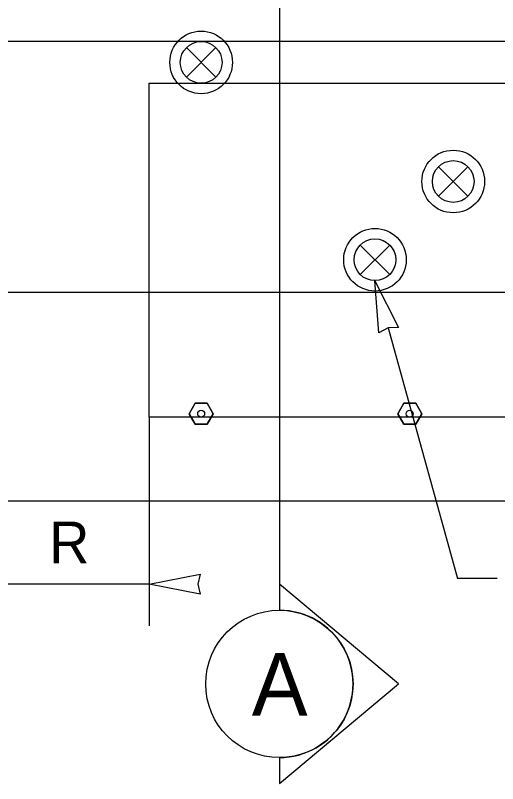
# Model space of a CAD drawing. Extents: x 99958 to 100176, y 99935 to 100011.
# Drawn here: x 100010.207 to 100011.132, y 99974.193 to 99975.666 of the extents above; entities that cross this region are included whole.
import ezdxf

# ---------------------------------------------------------------- set-up
doc = ezdxf.new("R2010")
doc.units = 0
for name, color, linetype in [('RD_ED_ShoulderPavedEdge', 7, 'Continuous'), ('RD_MK_LineEdgeWhite', 7, 'Continuous'), ('RD_MK_LineLane', 7, 'Continuous'), ('SH_TI_WZSectionCut', 7, 'Continuous'), ('TR_WZ_TrafficSafetyDrum', 7, 'Continuous'), ('TR_WZ_TubularMarker', 7, 'Continuous'), ('TR_WZ_WorkZoneDetails', 7, 'Continuous'), ('TR_WZ_WorkZoneTextCurrent', 7, 'Continuous')]:
    doc.layers.add(name, color=color, linetype=linetype)

msp = doc.modelspace()

# ---------------------------------------------------------------- linework, layer by layer
at = {"layer": 'RD_ED_ShoulderPavedEdge'}
msp.add_line((100000.8283, 99974.7357), (100014.8933, 99974.7357), dxfattribs=at)
at = {"layer": 'RD_MK_LineEdgeWhite'}
msp.add_line((100000.8283, 99975.1357), (100014.8933, 99975.1357), dxfattribs=at)
at = {"layer": 'RD_MK_LineLane'}
msp.add_lwpolyline([(100014.8933, 99975.6157), (100000.8283, 99975.6157)], dxfattribs=at)
at = {"layer": 'SH_TI_WZSectionCut'}
for p, q in [((100010.7136, 99976.1157), (100010.7136, 99974.5757)), ((100010.7136, 99974.5757), (100010.7136, 99974.5258)), ((100010.9417, 99974.3846), (100010.7136, 99974.5757)), ((100010.7136, 99974.1935), (100010.9417, 99974.3846)), ((100010.7136, 99974.2434), (100010.7136, 99974.1935))]:
    msp.add_line(p, q, dxfattribs=at)
msp.add_circle((100010.7136, 99974.3846), 0.1412, dxfattribs=at)
msp.add_arc((100010.7136, 99974.3846), 0.1412, 269.9978, 90.0022, dxfattribs=at)
at = {"layer": 'TR_WZ_TrafficSafetyDrum'}
for p, q in [((100010.5353, 99975.604), (100010.5919, 99975.5474)), ((100010.5919, 99975.604), (100010.5353, 99975.5474)), ((100011.0752, 99975.3192), (100011.0186, 99975.3757)), ((100011.0186, 99975.3192), (100011.0752, 99975.3757)), ((100010.9252, 99975.1692), (100010.8686, 99975.2257)), ((100010.8686, 99975.1692), (100010.9252, 99975.2257))]:
    msp.add_line(p, q, dxfattribs=at)
for centre, radius in [((100010.5636, 99975.5757), 0.06), ((100010.5636, 99975.5757), 0.06), ((100010.5636, 99975.5757), 0.04), ((100011.0469, 99975.3475), 0.06), ((100011.0469, 99975.3475), 0.06), ((100011.0469, 99975.3475), 0.04), ((100010.8969, 99975.1975), 0.06), ((100010.8969, 99975.1975), 0.06), ((100010.8969, 99975.1975), 0.04)]:
    msp.add_circle(centre, radius, dxfattribs=at)
at = {"layer": 'TR_WZ_TubularMarker'}
for points in [[(100010.5405, 99974.9024), (100010.5521, 99974.9224), (100010.5752, 99974.9224), (100010.5867, 99974.9024), (100010.5752, 99974.8824), (100010.5521, 99974.8824)], [(100010.9405, 99974.9024), (100010.9521, 99974.9224), (100010.9752, 99974.9224), (100010.9867, 99974.9024), (100010.9752, 99974.8824), (100010.9521, 99974.8824)]]:
    msp.add_lwpolyline(points, close=True, dxfattribs=at)
for points in [[(100010.5521, 99974.8824), (100010.5752, 99974.8824), (100010.5867, 99974.9024), (100010.5752, 99974.9224), (100010.5521, 99974.9224), (100010.5405, 99974.9024), (100010.5521, 99974.8824)], [(100010.9521, 99974.8824), (100010.9752, 99974.8824), (100010.9867, 99974.9024), (100010.9752, 99974.9224), (100010.9521, 99974.9224), (100010.9405, 99974.9024), (100010.9521, 99974.8824)]]:
    msp.add_lwpolyline(points, dxfattribs=at)
for centre in [(100010.5636, 99974.9024), (100010.9636, 99974.9024)]:
    msp.add_circle(centre, 0.00667, dxfattribs=at)
at = {"layer": 'TR_WZ_WorkZoneDetails'}
for p, q in [((100010.9219, 99975.0671), (100011.0551, 99974.5867)), ((100010.4636, 99974.8957), (100010.4636, 99974.4957)), ((100011.1313, 99974.5867), (100011.0551, 99974.5867)), ((100010.4636, 99974.5757), (100010.1557, 99974.5757))]:
    msp.add_line(p, q, dxfattribs=at)
for points in [[(100010.4636, 99974.8957), (100010.4636, 99975.5357), (100012.9636, 99975.5357), (100012.9636, 99974.8957)], [(100010.8969, 99975.1574), (100010.9417, 99975.0678), (100010.9219, 99975.0671), (100010.9045, 99975.0575)], [(100010.4636, 99974.5757), (100010.5619, 99974.595), (100010.5573, 99974.5757), (100010.5619, 99974.5565)]]:
    msp.add_lwpolyline(points, close=True, dxfattribs=at)

# ---------------------------------------------------------------- texts
at = {"layer": 'SH_TI_WZSectionCut'}
msp.add_text('A', height=0.12, rotation=0.01, dxfattribs=at).set_placement((100010.6607, 99974.3237))
at = {"layer": 'TR_WZ_WorkZoneTextCurrent'}
msp.add_text('R', height=0.08, dxfattribs=at).set_placement((100010.2721, 99974.6157))

doc.saveas('drawing.dxf')
